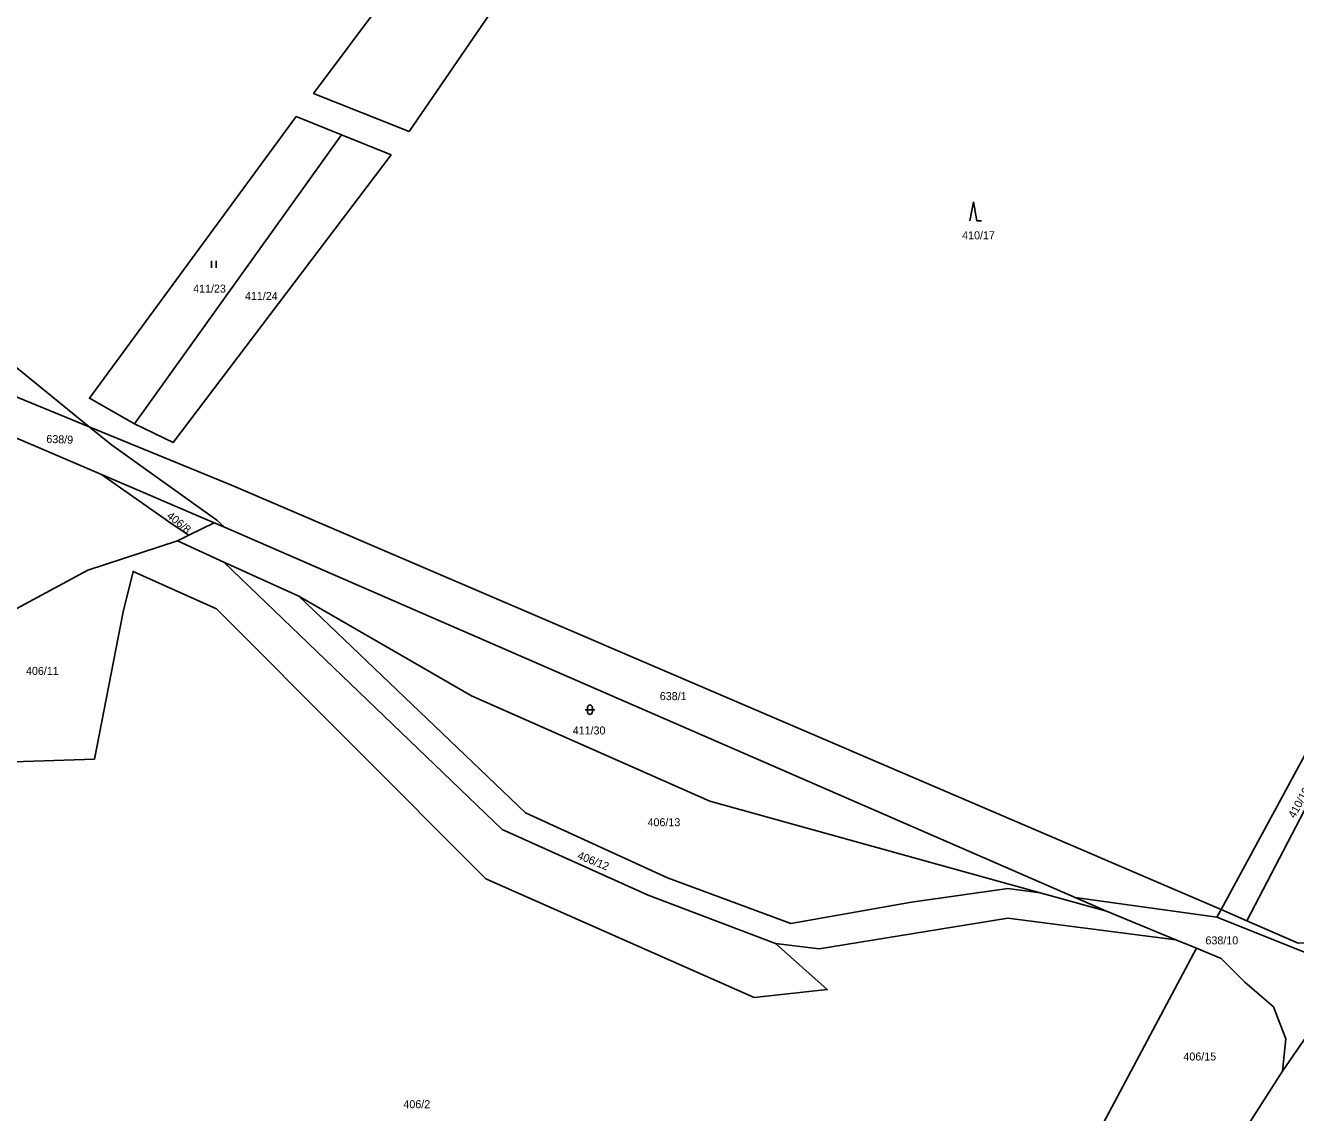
# Model space of a CAD drawing. Extents: x -744566 to -741843, y -1128407 to -1126744.
# Drawn here: x -743925.6 to -743655.8, y -1127273.4 to -1127042.4 of the extents above; entities that cross this region are included whole.
import ezdxf

# ---------------------------------------------------------------- set-up
doc = ezdxf.new("R2010")
doc.units = 0
for name, color, linetype in [('Hranice parcel', 7, 'Continuous'), ('Parcelní čísla', 7, 'Continuous'), ('Značky kultur', 7, 'Continuous')]:
    doc.layers.add(name, color=color, linetype=linetype)

msp = doc.modelspace()

# ---------------------------------------------------------------- linework, layer by layer
at = {"layer": 'Hranice parcel'}
for p, q in [((-743864.42, -1127056.89), (-743816.04, -1126992.08)), ((-743801.36, -1127002.53), (-743844.13, -1127064.95)), ((-743844.13, -1127064.95), (-743864.42, -1127056.89)), ((-743868.09, -1127061.76), (-743858.46, -1127065.61)), ((-743902.46, -1127127.03), (-743858.46, -1127065.61)), ((-743858.46, -1127065.61), (-743847.95, -1127069.9)), ((-743932.71, -1127119.19), (-743912.07, -1127127.67)), ((-743885.49, -1127148.05), (-743909.45, -1127137.8)), ((-743890.91, -1127150.72), (-743885.49, -1127148.05)), ((-743885.49, -1127148.05), (-743883.35, -1127148.98)), ((-743883.35, -1127148.98), (-743702.59, -1127227.7)), ((-743893.34, -1127151.92), (-743890.91, -1127150.72)), ((-743883.44, -1127156.41), (-743893.34, -1127151.92)), ((-743867.51, -1127163.63), (-743883.44, -1127156.41)), ((-743671.64, -1127230.23), (-743646.48, -1127183.8)), ((-743666.12, -1127232.6), (-743642.12, -1127186.45)), ((-743695.97, -1127230.58), (-743710.09, -1127226.67)), ((-743702.59, -1127227.7), (-743695.97, -1127230.58)), ((-743702.59, -1127227.7), (-743672.5, -1127231.82)), ((-743672.5, -1127231.82), (-743671.64, -1127230.23)), ((-743671.64, -1127230.23), (-743666.12, -1127232.6)), ((-743681.2, -1127236.66), (-743695.97, -1127230.58)), ((-743643.98, -1127243.27), (-743672.5, -1127231.82)), ((-743676.81, -1127238.46), (-743681.2, -1127236.66)), ((-743643.98, -1127243.27), (-743658.6, -1127264.57)), ((-743658.6, -1127264.57), (-743689.23, -1127312.32))]:
    msp.add_line(p, q, dxfattribs=at)
for points in [[(-743902.46, -1127127.03), (-743912.04, -1127121.62), (-743868.09, -1127061.76)], [(-743847.95, -1127069.9), (-743894.24, -1127131.03), (-743902.46, -1127127.03)], [(-743912.07, -1127127.67), (-743939.05, -1127105.74), (-743980.2, -1127091.58)], [(-743909.45, -1127137.8), (-743939.63, -1127124.9), (-743941.59, -1127124.09)], [(-743671.64, -1127230.23), (-743881.84, -1127140.1), (-743912.07, -1127127.67)], [(-743912.07, -1127127.67), (-743907.34, -1127131.52), (-743884.95, -1127147.5), (-743883.35, -1127148.98)], [(-743890.91, -1127150.72), (-743894.04, -1127148.63), (-743909.45, -1127137.8)], [(-743969.78, -1127189.05), (-743912.35, -1127158.14), (-743893.34, -1127151.92)], [(-743766.29, -1127237.43), (-743793.36, -1127227.19), (-743824.36, -1127213.25), (-743883.44, -1127156.41)], [(-743766.29, -1127237.43), (-743755.28, -1127247.25), (-743770.82, -1127248.95), (-743827.84, -1127223.67), (-743885.04, -1127166.35), (-743902.74, -1127158.4), (-743904.83, -1127167), (-743910.98, -1127198.27), (-743973.54, -1127200.34)], [(-743710.09, -1127226.67), (-743716.91, -1127225.73), (-743737.38, -1127228.65), (-743763.04, -1127233.2), (-743789.24, -1127223.49), (-743819.38, -1127209.69), (-743867.51, -1127163.63)], [(-743710.09, -1127226.67), (-743780.26, -1127207.21), (-743830.86, -1127184.8), (-743867.51, -1127163.63)], [(-743681.2, -1127236.66), (-743716.91, -1127232.07), (-743757.03, -1127238.57), (-743766.29, -1127237.43)], [(-743666.12, -1127232.6), (-743655.22, -1127237.38), (-743645.09, -1127236.9), (-743636.37, -1127232.18)], [(-743689.23, -1127312.32), (-743706.45, -1127294.03), (-743676.81, -1127238.46)], [(-743658.6, -1127264.57), (-743657.88, -1127257.69), (-743660.49, -1127250.92), (-743666.59, -1127245.69), (-743671.57, -1127240.62), (-743676.81, -1127238.46)]]:
    msp.add_lwpolyline(points, dxfattribs=at)
at = {"layer": 'Značky kultur'}
for p, q in [((-743724.23, -1127079.9), (-743724.98, -1127083.9)), ((-743723.48, -1127083.9), (-743724.23, -1127079.9)), ((-743723.48, -1127083.9), (-743722.484, -1127083.9)), ((-743886.071, -1127093.9), (-743886.071, -1127092.4)), ((-743885.07, -1127093.9), (-743885.07, -1127092.4)), ((-743806.691, -1127187.771), (-743804.689, -1127187.771)), ((-743806.191, -1127187.271), (-743806.191, -1127188.272)), ((-743805.189, -1127188.272), (-743805.189, -1127187.271))]:
    msp.add_line(p, q, dxfattribs=at)
for centre, start, end in [((-743805.69, -1127187.271), 0, 180), ((-743805.69, -1127188.271), 180, 359.98789)]:
    msp.add_arc(centre, 0.5, start, end, dxfattribs=at)

# ---------------------------------------------------------------- texts
at = {"layer": 'Parcelní čísla'}
for s, p in [('410/17', (-743726.63, -1127087.83)), ('411/23', (-743889.985, -1127099.16)), ('411/24', (-743878.985, -1127100.73)), ('406/11', (-743925.5, -1127180.38)), ('638/1', (-743790.86, -1127185.74)), ('411/30', (-743809.365, -1127193.03)), ('406/13', (-743793.46, -1127212.53)), ('638/10', (-743674.94, -1127237.63)), ('406/15', (-743679.62, -1127262.3)), ('406/2', (-743845.32, -1127272.43))]:
    msp.add_text(s, height=1.7, dxfattribs=at).set_placement(p)
for s, rotation, p in [('638/9', 358, (-743921.199, -1127131.079)), ('406/8', 321, (-743895.744, -1127146.86)), ('410/19', 61, (-743655.996, -1127210.972)), ('406/12', 338, (-743808.518, -1127219.368))]:
    msp.add_text(s, height=1.7, rotation=rotation, dxfattribs=at).set_placement(p)

doc.saveas('drawing.dxf')
